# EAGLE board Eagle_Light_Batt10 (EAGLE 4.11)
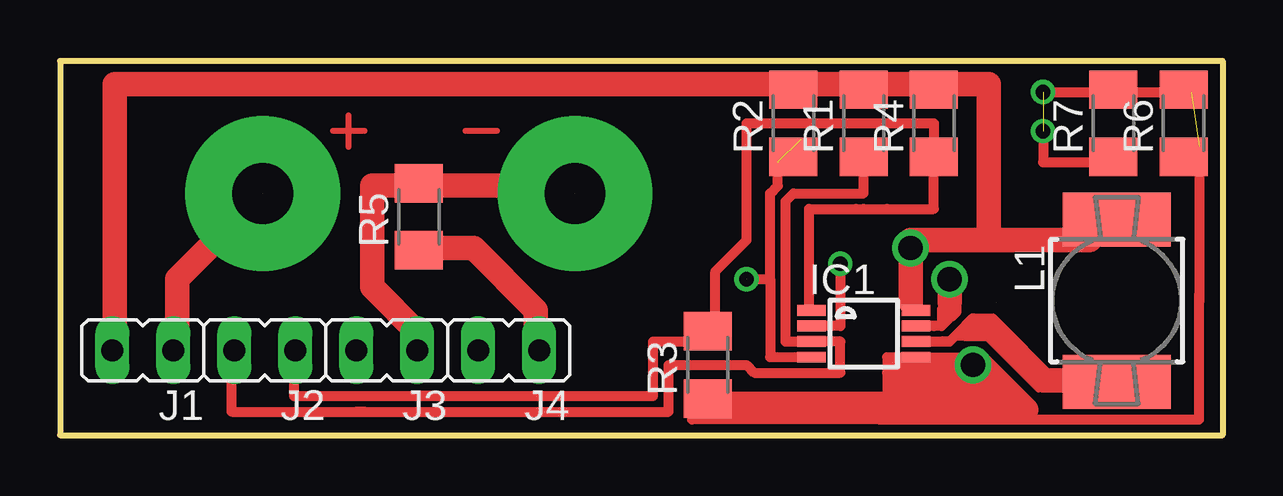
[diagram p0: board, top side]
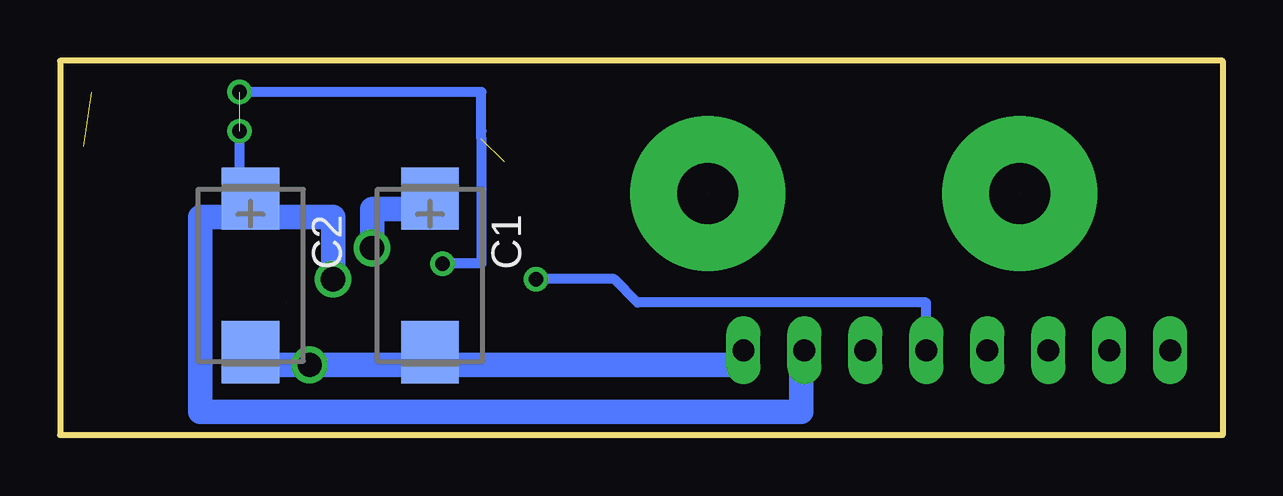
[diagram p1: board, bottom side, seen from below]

Size 48.44 x 15.61 mm. Coordinates in mm from the lower left corner, seen from the top.
Outline: 48.44,15.61 48.44,0 0,0 0,15.61 48.44,15.61
Copper layers (1*16): Top 0.035mm / dielectric 1.5mm / Bottom 0.035mm
Design rules "default": minimum track width 10mil, minimum drill 24mil, track to track 8mil, track to pad 8mil, pad to pad 8mil, via to via 8mil, smd to smd 8mil, copper to edge 40mil, drill to drill 8mil, minimum pad ring 10mil, minimum via ring 8mil, stop-mask expansion 4mil, vias tented up to drill 0mil, thermal gap 10mil

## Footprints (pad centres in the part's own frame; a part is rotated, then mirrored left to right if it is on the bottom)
CT7343 = smd 2.6 x 2.4: + -3.2,0; - 3.2,0
UMAX8 = smd 0.45 x 1.2: 1 -0.975,-2.175; 2 -0.325,-2.175; 3 0.325,-2.175; 4 0.975,-2.175; 5 0.975,2.175; 6 0.325,2.175; 7 -0.325,2.175; 8 -0.975,2.175
JP1 = drill 0.914 long: 1 0,-1.27; 2 0,1.27
MS85 = smd 4.5 x 2.25: 1 0,-3.383; 2 0,3.383
M1206 = smd 1.6 x 2: 1 -1.4,0; 2 1.4,0

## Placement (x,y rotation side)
C1  47µ  [CT7343]  33.02,6.67 270 bottom
C2  47µ  [CT7343]  40.5,6.66 270 bottom
IC1  MAX1797  [UMAX8]  33.49,4.23 270 top
J1  B+* B+  [JP1]  3.45,3.54 90 top
J2  SHDN LBI  [JP1]  8.53,3.54 90 top
J3  LBO B-  [JP1]  13.61,3.54 90 top
J4  +5V GND  [JP1]  18.69,3.54 90 top
L1  22µ  [MS85]  44.03,5.61 180 top
R1  1M  [M1206]  33.49,13 90 top
R2  1M  [M1206]  30.56,13 90 top
R3  220k  [M1206]  26.99,2.93 90 top
R4  560k  [M1206]  36.41,13 90 top
R5  0,56  [M1206]  14.96,9.1 90 top
R6  1M  [M1206]  46.82,13 90 top
R7  1M  [M1206]  43.89,13 90 top

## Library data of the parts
C1 C2 R1-R7 = smd-ipc
IC1 = maxim
J1-J4 = jumper
L1 = inductor-neosid

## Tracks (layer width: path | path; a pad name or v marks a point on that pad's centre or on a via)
C2  (via drill 1.02)
  Top 0.406: 36.74,4.55 36.09,4.55 | 36.74,4.55 36.41,4.55 | 36.74,4.55 37.06,4.88 37.06,5.53
  Top 1.016: 37.06,5.53 | v37.06,6.5 37.06,5.53
  Bottom 1.016: v37.06,6.5 37.06,9.1 42.59,9.1 42.59,6.18 | 42.59,6.18 42.59,6.5 | 42.59,6.18 42.59,0.98 19.83,0.98
S$1
  Top 1.016: 42.59,2.28 40.97,2.28 39.01,4.23
S$2
  Bottom 1.016: 20.16,0.98 17.56,0.98 17.56,3.58
S$3
  Top 0.406: 35.76,3.9 37.06,3.9 | 37.06,3.9 36.74,3.9 | 37.06,3.9 37.39,4.23 | 37.39,4.23 38.04,4.88 | 37.71,4.23 37.39,4.23
  Top 0.61: 40.64,2.28 38.69,4.23 37.71,4.23
S$4  (via drill 0.61)  (11 unrouted)
  Top 0.406: 34.14,0.65 34.46,0.65 | 34.46,0.65 35.11,0.65 | 35.11,0.65 47.47,0.65 47.47,5.85 | 47.47,12.03 47.47,5.85 | 47.47,5.85 47.47,5.53 | 43.89,11.38 40.97,11.38 v40.97,12.68 | 31.86,4.55 32.51,4.55 v32.51,7.15 | v40.97,14.31 47.14,14.31 | 29.91,11.38 29.91,10.4 29.59,10.08 29.59,6.5 | 31.21,3.25 29.59,3.25 29.59,6.5 | v28.61,6.5 29.59,6.5 | 34.46,0.65 26.33,0.65 | 35.11,0.65 35.11,2.6
  Bottom 0.406: v40.97,12.68 40.97,10.4 | v40.97,14.31 30.89,14.31 30.89,12.35 | v32.51,7.15 30.89,7.15 30.89,12.35 | 30.89,12.35 30.89,12.68 | v28.61,6.5 25.36,6.5 24.38,5.53 12.35,5.53 12.35,3.25
S$5
  Top 0.406: 35.11,3.25 34.46,3.25 34.46,2.6
S$7  (2 unrouted)
S$8
  Top 1.016: 38.69,4.55 38.36,4.55
S$9  (via drill 2.54 pad 6.45)  (1 unrouted)
  Top 1.016: v8.45,10.08 4.88,6.5 4.88,3.58
S$10
  Top 0.406: 26.33,3.9 24.71,3.9 24.71,1.63 15.61,1.63 | 15.61,1.63 14.96,1.63 | 15.61,1.63 9.75,1.63 9.75,3.58
S$11
  Top 0.254: 37.75,4.05 37.33,4.05
S$12
  Top 0.254: 38.06,4.94 38.9,4.94 38.83,4.92
S$13
  Top 0.406: 27.31,4.88 27.31,6.83 28.61,8.13 28.61,13 36.41,13 36.41,11.7
S$14
  Top 1.016: 2.28,3.58 2.28,14.63 30.24,14.63
S$15
  Top 0.254: 38.91,4.92 41.6,2.23
S$16
  Top 0.254: 18.21,12.68 16.91,12.68
S$17
  Top 0.254: 38.75,3.93 38.75,3.92 40.77,1.9
S$18
  Top 0.254: 12.68,12.68 11.38,12.68
S$19
  Top 0.254: 12.03,12.03 12.03,13.33
S$20
  Top 1.016: 30.89,14.63 36.74,14.63
S$21  (via drill 2.54 pad 6.45)  (1 unrouted)
  Top 1.016: 15.28,10.4 21.13,10.4 v21.46,10.08 | v21.46,10.08 | v21.46,10.08 22.11,9.43
S$22  (via drill 1.02)
  Top 1.016: 37.06,14.63 38.69,14.63 38.69,8.13 38.36,8.13 | 38.36,8.13 35.44,8.13 35.44,6.5 | 35.44,5.53 35.44,6.5 | 35.44,6.5 v35.44,7.8 | 38.36,8.13 42.92,8.13
  Bottom 1.016: v35.44,7.8 35.44,9.43 33.16,9.43
S$23
  Top 0.406: 33.16,9.43 31.21,9.43 31.21,5.2 | 33.16,9.43 33.49,9.43 | 33.16,9.43 34.46,9.43 | 34.46,9.43 | 34.46,9.43 36.41,9.43 36.41,11.05
S$24
  Top 0.406: 30.56,10.08 30.24,9.75 30.24,3.9 31.21,3.9 | 30.56,10.08 | 30.56,10.08 33.49,10.08 33.49,11.38
S$25
  Top 1.016: 19.83,3.58 19.83,5.2 17.23,7.8 15.28,7.8
S$26
  Top 1.016: 14.31,10.4 13,10.4 13,6.18 14.96,4.23 14.96,3.25
S$27
  Top 0.406: 31.86,3.9 32.51,3.9 32.51,2.6 28.94,2.6 28.61,2.93 25.36,2.93 25.36,0.98 12.68,0.98 | 12.68,0.98 12.35,0.98 | 12.68,0.98 7.15,0.98 7.15,3.58
S$28  (via drill 1.02)
  Top 1.016: 27.31,1.3 34.79,1.3 34.79,2.93 v38.04,2.93 | 38.07,2.93 38.07,1.05 38.04,1.03 35,1.03 34.93,1.1 34.93,2.2 35.01,2.29 37.56,2.29 37.71,2.13 37.71,1.78 37.68,1.75 35.57,1.75 35.55,1.76 | 38.08,3 38.3,3 40.25,1.05 38.65,1.05 38.37,1.33 38.37,1.38 38.7,1.71
  Bottom 1.016: 19.83,3.58 19.83,2.93 v38.04,2.93 39.99,2.93 39.99,3.9
S$29
  Top 0.254: 36.75,4.75 36.75,5.34 36.76,5.35
S$30
  Top 0.254: 37.21,4.88 | 37.21,4.88 37.44,5.12 37.44,5.52 37.42,5.54
S$31
  Top 0.254: 36.68,4.72 36.68,5.29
